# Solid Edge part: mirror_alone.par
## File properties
Author: Owner
Template: Iso Part.par
Last saved by: Owner
Revision: 29
Application: Solid Edge
Material: Silver
Face Style: Silver
Fill Style: ANSI31(Iron)
Virtual Style: Silver
Coef. of Thermal Exp: 1e-05
Thermal Conductivity: 419.0
Specific Heat: 234.0
Modulus of Elasticity: 75842327000.0
Poisson's Ratio: 0.38
Yield Stress: 303369308.0
Ultimate Stress: 344737850.0
Elongation: 0.0
Density: 1.050e+004 kg/m^3
Accuracy: 0.990
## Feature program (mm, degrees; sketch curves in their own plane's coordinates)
sketch for "unnamed RevolvedProtrusion 1" plane through (0, 0, 0) normal (0, -1, 0) x-axis (1, 0, 0)
  line (0, -86.784) -> (1000, -86.784)
  line (1000, -86.784) -> (1000, 641.7424)
  arc centre (0, 1100) radius 1100 from (0, 0) to (1000, 641.7424) ccw
  line (0, 0) -> (0, -86.784)
revolve "unnamed RevolvedProtrusion 1" add full turn 360 deg
thinwall "Thinwall_1"  Thickness = 3 mm
sketch for "unnamed Cutout 1" #1 plane through (0, 0, -86.784) normal (0, 0, -1) x-axis (-1, 0, 0)
  line (300, 275) -> (300, -275)
  line (300, -275) -> (-300, -275)
  line (-300, -275) -> (-300, 275)
  line (-300, 275) -> (300, 275)
sketch for "unnamed Cutout 1" #2 plane through (0, 0, -86.784) normal (0, 0, -1) x-axis (-1, 0, 0)
  circle centre (0, 0) radius 1152.023
extrude "unnamed Cutout 1" cut finite 850 along -normal
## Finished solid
Body 1: solid body, 6 faces, 12 edges, 8 vertices.
  Faces by surface: plane 4, sphere 2
  Edges by curve: circle 8, line 4
Bounding box of the edges (mm; curved faces can reach further): 600.000 x 550.000 x 46.222, from (-300, -275, 31.8315) to (300, 275, 78.0533).
Spherical faces by radius (mm): R1100 x1, R1103 x1
Planar faces by outward normal: +x 1, +y 1, -x 1, -y 1
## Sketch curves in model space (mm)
arc centre (-225, -225, 0) radius 20 from (-232.5, -206.4595, 0) through (-238.2724, -239.9614, 0) to (-206.4595, -232.5, 0)
line (-206.4595, -232.5, 0) -> (6.6589, -232.5, 0)
line (6.6589, -232.5, 0) -> (232.5, -6.6589, 0)
line (232.5, 206.4595, 0) -> (232.5, -6.6589, 0)
arc centre (225, 225, 0) radius 20 from (206.4595, 232.5, 0) through (239.9614, 238.2724, 0) to (232.5, 206.4595, 0)
line (-206.4595, 232.5, 0) -> (206.4595, 232.5, 0)
arc centre (-225, 225, 0) radius 20 from (-206.4595, 232.5, 0) through (-239.9614, 238.2724, 0) to (-232.5, 206.4595, 0)
line (-232.5, 206.4595, 0) -> (-232.5, -206.4595, 0)
arc centre (-225, -225, 0) radius 20 from (-206.4595, -217.5, 0) through (-210.8579, -210.8579, 0) to (-217.5, -206.4595, 0)
line (-206.4595, -217.5, 0) -> (0, -217.5, 0)
line (0, -217.5, 0) -> (217.5, 0, 0)
line (217.5, 206.4595, 0) -> (217.5, 0, 0)
arc centre (225, 225, 0) radius 20 from (206.4595, 217.5, 0) through (210.8579, 210.8579, 0) to (217.5, 206.4595, 0)
line (-206.4595, 217.5, 0) -> (206.4595, 217.5, 0)
arc centre (-225, 225, 0) radius 20 from (-206.4595, 217.5, 0) through (-210.8579, 210.8579, 0) to (-217.5, 206.4595, 0)
line (-217.5, 206.4595, 0) -> (-217.5, -206.4595, 0)
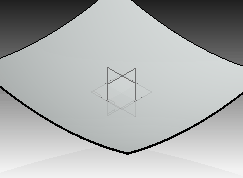
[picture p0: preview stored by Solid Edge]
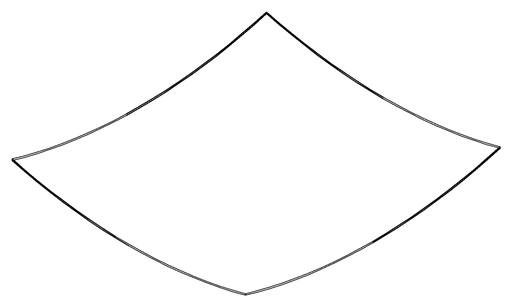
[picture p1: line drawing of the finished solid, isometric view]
